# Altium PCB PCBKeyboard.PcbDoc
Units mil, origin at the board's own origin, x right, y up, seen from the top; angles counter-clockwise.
Board outline 2655 x 4800 mil, 2 copper layers (Top Layer, Bottom Layer); 24 components, 13 nets, 98 pads, 4 vias.
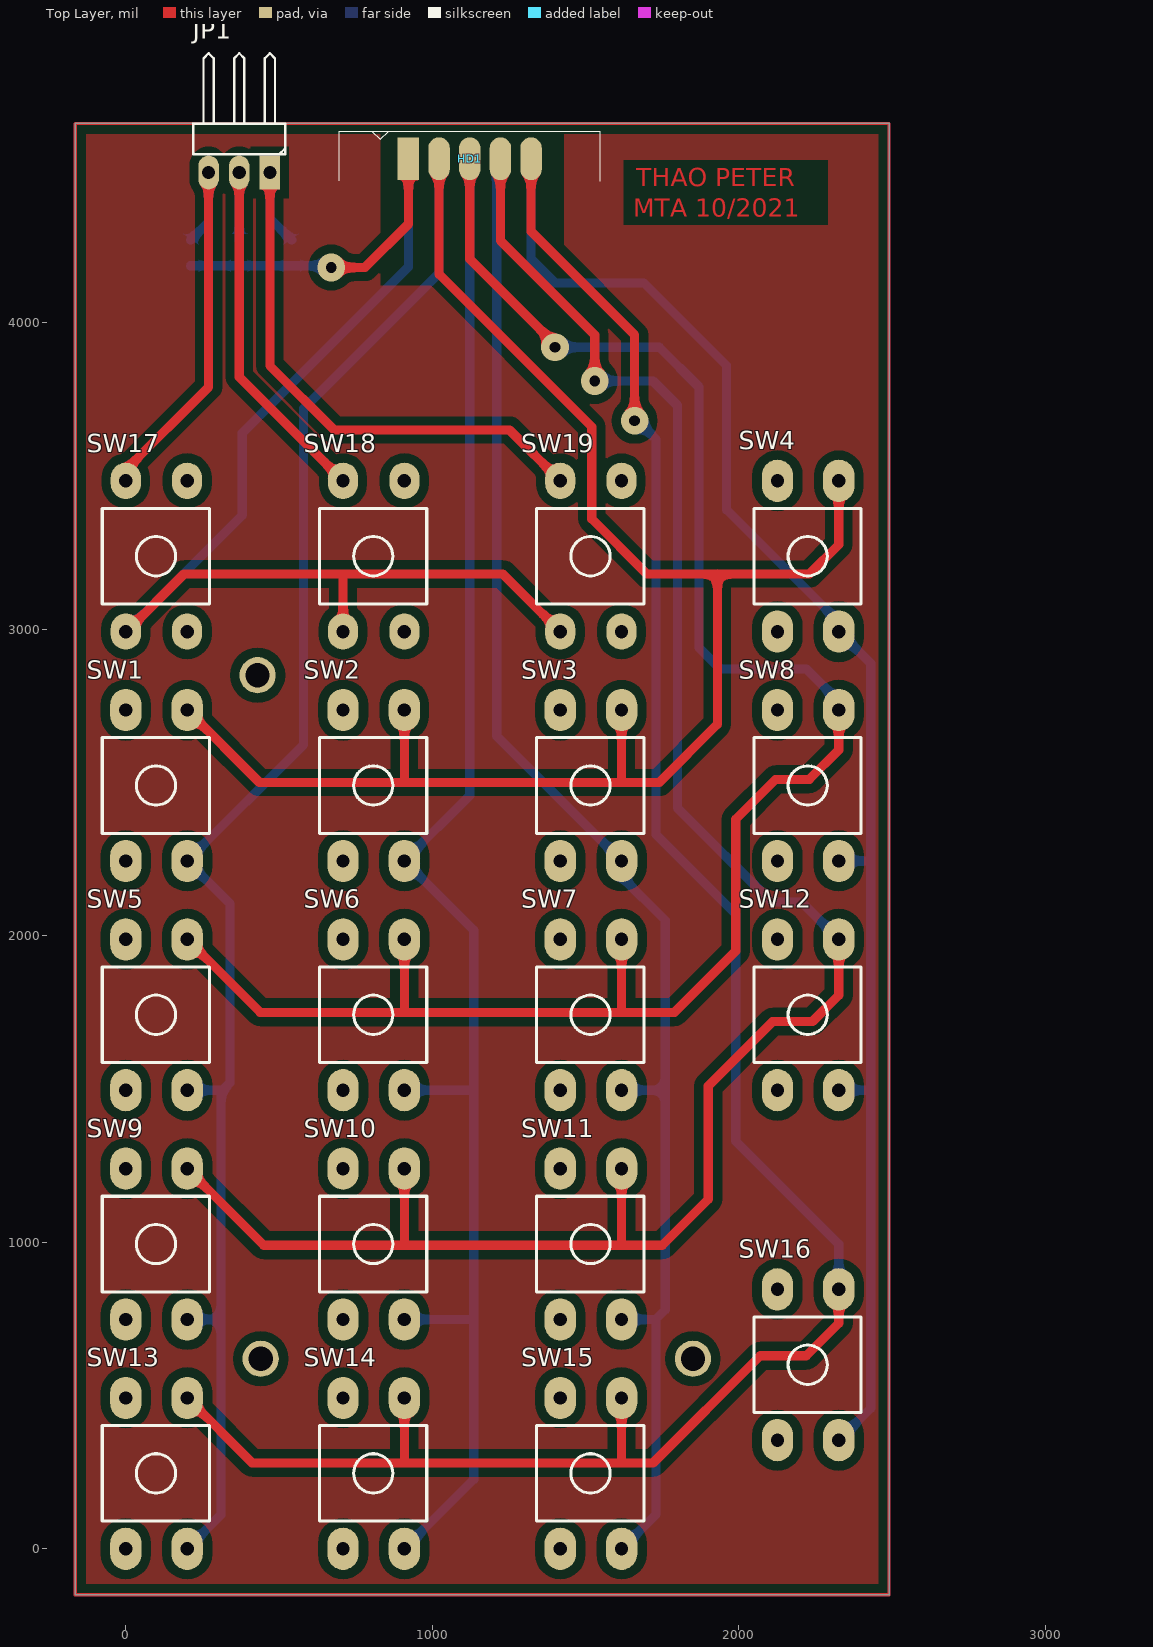
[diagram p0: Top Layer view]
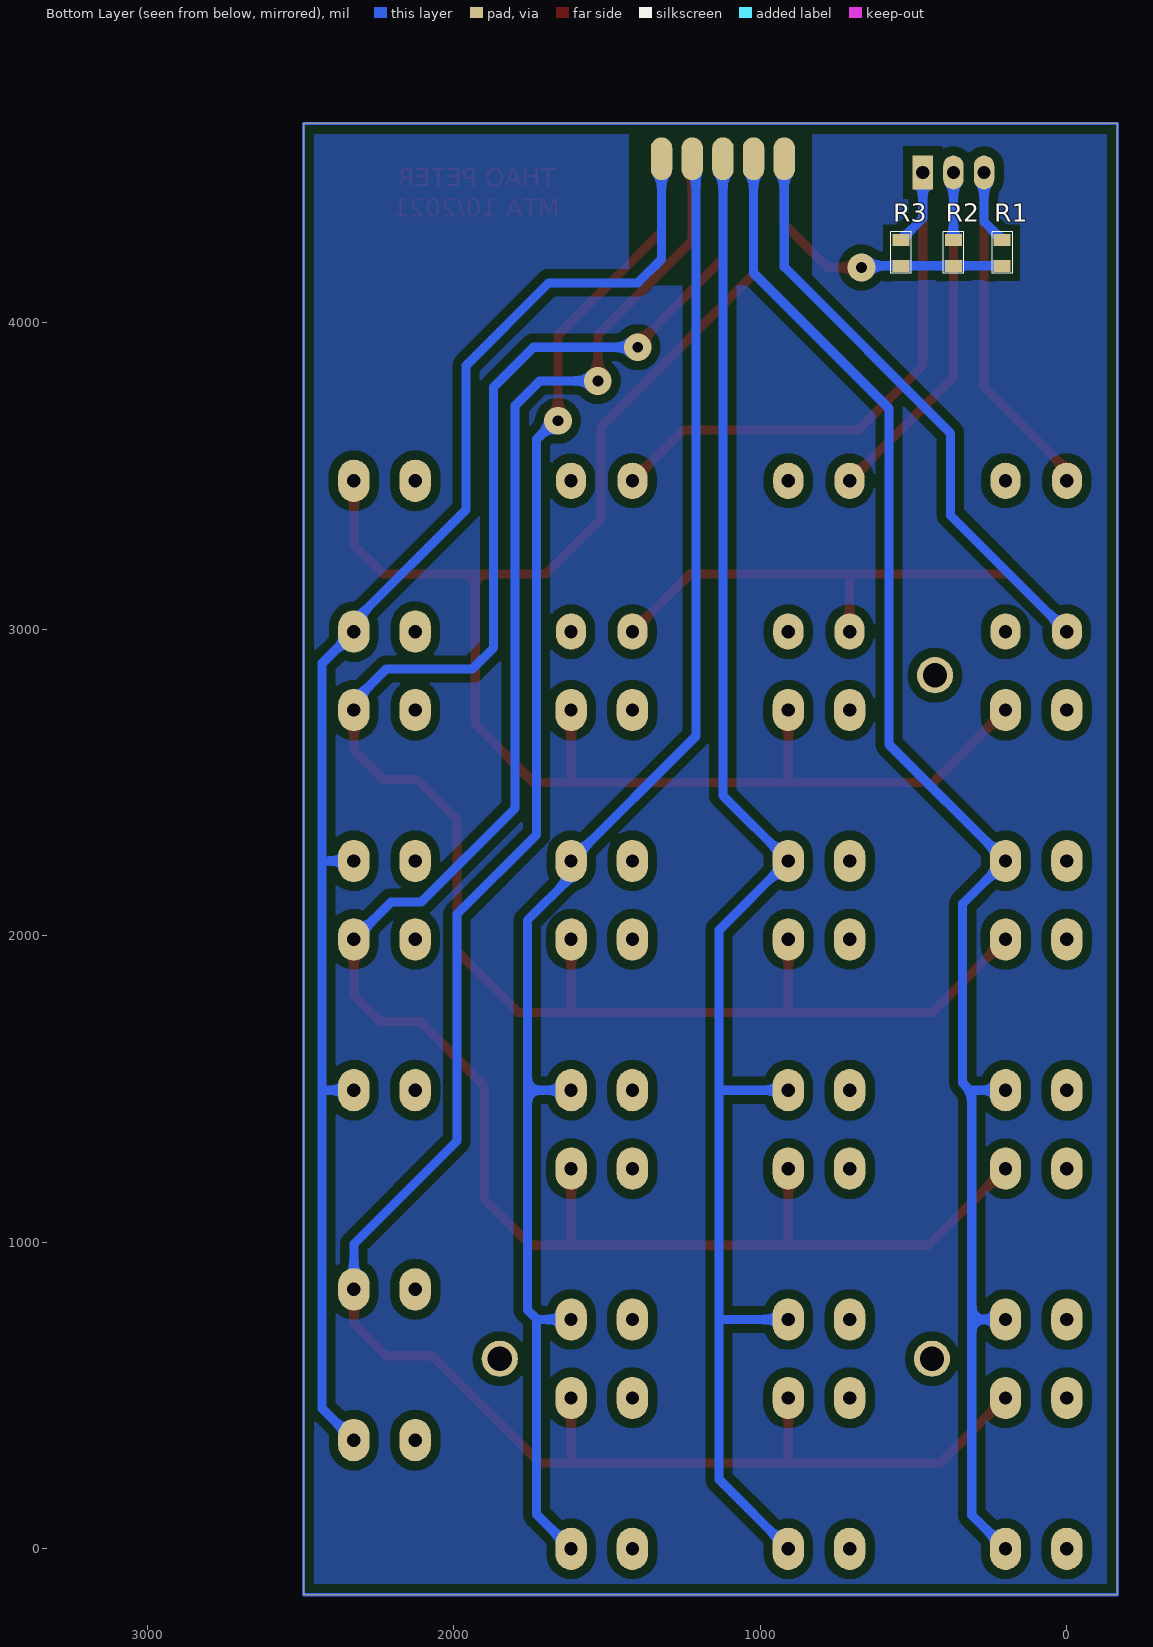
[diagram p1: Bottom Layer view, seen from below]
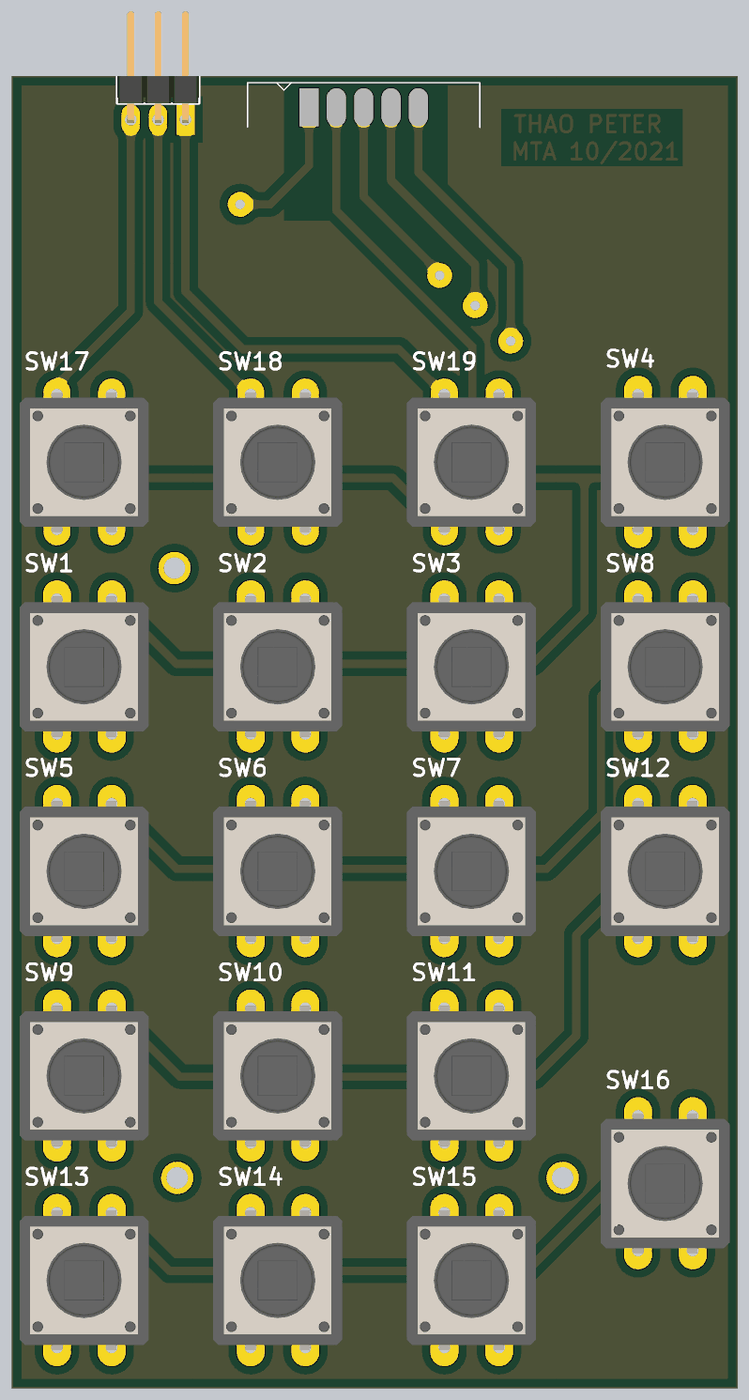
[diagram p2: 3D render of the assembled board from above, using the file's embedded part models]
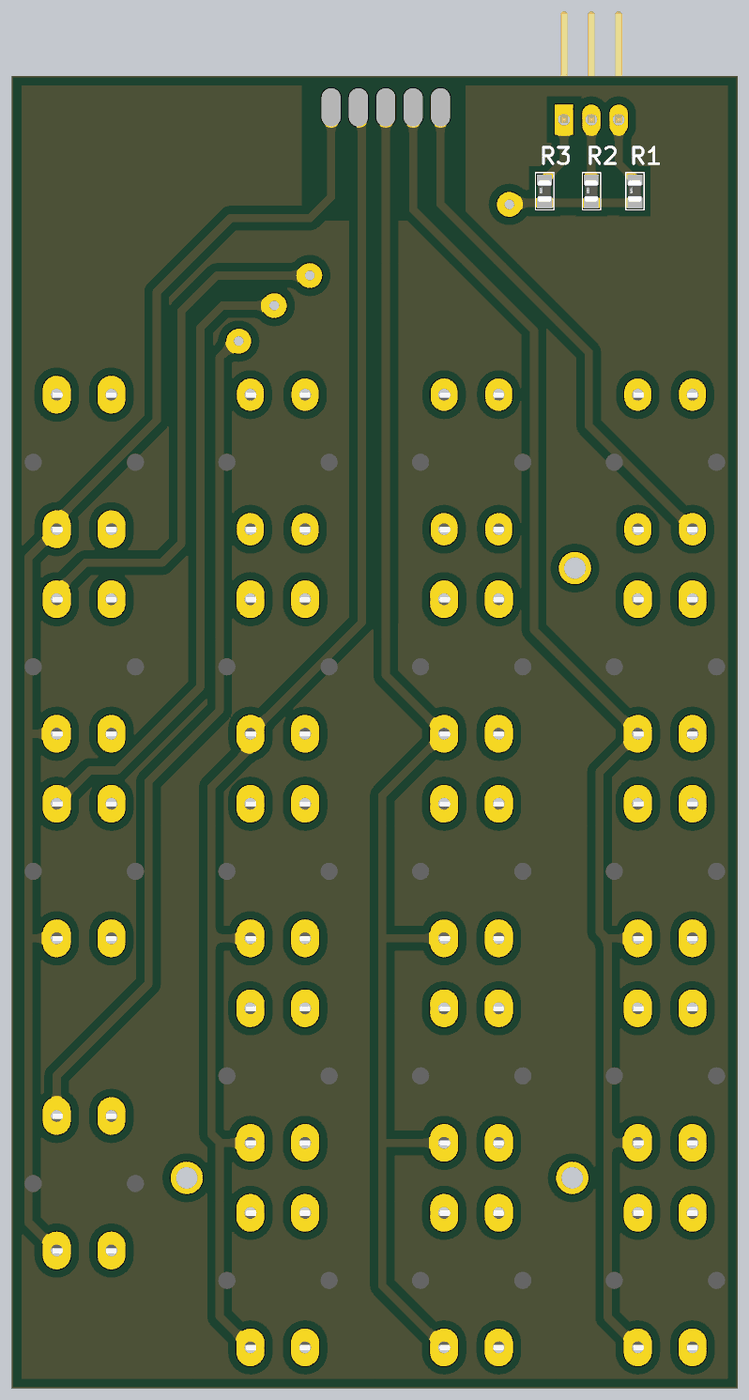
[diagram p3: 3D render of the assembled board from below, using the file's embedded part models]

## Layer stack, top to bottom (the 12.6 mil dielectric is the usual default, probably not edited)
Top Solder: solder mask 0.4, Solder Resist, Dk 3.5
Top Layer: signal copper 1.4
Dielectric 1: dielectric 12.6, FR-4, Dk 4.8
Bottom Layer: signal copper 1.4
Bottom Solder: solder mask 0.4, Solder Resist, Dk 3.5

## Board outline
-165,-150 2490,-150 2490,4650 -165,4650

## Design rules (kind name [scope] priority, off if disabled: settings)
Clearance [All] p1: gap=30 ignorepadtopadclearanceinfootprint=FALSE
PolygonConnect [All] p1: connectstyle=Relief reliefconductorwidth=10 reliefentries=4 polygonreliefangle="90 Angle" airgapwidth=10
RoutingVias [All] p1: holewidth=28 width=50 viastyle="Through Hole" minholewidth=28 minwidth=50 maxholewidth=28 maxwidth=50
SolderMaskExpansion [All] p1: expansion=4
Width [All] p1: maxlimit=100 minlimit=10 preferedwidth=30
30 further rules are at their usual default settings.

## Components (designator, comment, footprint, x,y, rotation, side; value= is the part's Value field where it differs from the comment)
HD1 "IDC 5X2" IDC10-S 1122.05,4700 r0 top value="Header 5x2"
JP1 "JP3" JP3-D1C 220,4590 r180 top
R1 "10k" RES-SMD-0805 211,4185.62 r90 bottom
R2 "10k" RES-SMD-0805 369.99,4185.62 r90 bottom
R3 "10k" RES-SMD-0805 541,4185.62 r90 bottom
SW1 "SW" "BUTTON 12mm"#1 0,2244.09 r90 top value="Button chip 4 pin"
SW2 "SW" "BUTTON 12mm"#1 708.66,2244.09 r90 top value="Button chip 4 pin"
SW3 "SW" "BUTTON 12mm"#1 1417.32,2244.09 r90 top value="Button chip 4 pin"
SW4 "SW" "BUTTON 12mm"#1 2125.98,2992.13 r90 top value="Button chip 4 pin"
SW5 "SW" "BUTTON 12mm"#1 0,1496.06 r90 top value="Button chip 4 pin"
SW6 "SW" "BUTTON 12mm"#1 708.66,1496.06 r90 top value="Button chip 4 pin"
SW7 "SW" "BUTTON 12mm"#1 1417.32,1496.06 r90 top value="Button chip 4 pin"
SW8 "SW" "BUTTON 12mm"#1 2125.98,2244.09 r90 top value="Button chip 4 pin"
SW9 "SW" "BUTTON 12mm"#1 0,748.03 r90 top value="Button chip 4 pin"
SW10 "SW" "BUTTON 12mm"#1 708.66,748.03 r90 top value="Button chip 4 pin"
SW11 "SW" "BUTTON 12mm"#1 1417.32,748.03 r90 top value="Button chip 4 pin"
SW12 "SW" "BUTTON 12mm"#1 2125.98,1496.06 r90 top value="Button chip 4 pin"
SW13 "SW" "BUTTON 12mm"#1 0,0 r90 top value="Button chip 4 pin"
SW14 "SW" "BUTTON 12mm"#1 708.66,0 r90 top value="Button chip 4 pin"
SW15 "SW" "BUTTON 12mm"#1 1417.32,0 r90 top value="Button chip 4 pin"
SW16 "SW" "BUTTON 12mm"#1 2125.98,354.33 r90 top value="Button chip 4 pin"
SW17 "SW" "BUTTON 12mm"#2 0,2992.13 r90 top value="Button chip 4 pin"
SW18 "SW" "BUTTON 12mm"#2 708.66,2992.13 r90 top value="Button chip 4 pin"
SW19 "SW" "BUTTON 12mm"#2 1417.32,2992.13 r90 top value="Button chip 4 pin"

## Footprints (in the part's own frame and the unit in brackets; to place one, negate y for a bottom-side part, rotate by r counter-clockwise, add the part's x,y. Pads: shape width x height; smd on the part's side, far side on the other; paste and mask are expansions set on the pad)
"BUTTON 12mm"#1 [mm]
  oval 3.5x2.6 hole 1.1: 1(0,0) 2(12.5,0) 3(12.5,-5.08) 4(0,-5.08)
  silkscreen extent 2.29,-6.93 10.21,1.96, body extent -0.28,-8.51 12.72,3.49, height 7.3
"BUTTON 12mm"#2 [mm]
  oval 3x2.5 hole 1.1: 1(0,0) 2(12.5,0) 3(12.5,-5.08) 4(0,-5.08)
  silkscreen extent 2.29,-6.93 10.21,1.96, body extent -0.28,-8.51 12.72,3.49, height 7.3
IDC10-S [mil]
  rect 70x140 smd: 1(-200,-165)
  oval 70x140 smd far side: 2(-200,-165) 4(-100,-165) 6(0,-165) 8(100,-165) 10(200,-165)
  oval 70x140 smd: 3(-100,-165) 5(0,-165) 7(100,-165) 9(200,-165)
  silkscreen extent -425,-239 425,-75, body extent -425,-238 426,276, height 151
JP3-D1C [mm] "3 pins, 1 row, right angled, gold plating"
  rect 1.7x2.8 hole 1.1: 1(-6.35,2.54)
  oval 1.7x2.8 hole 1.1: 2(-3.81,2.54) 3(-1.27,2.54)
  silkscreen extent -7.62,-7.34 0,1.04, body extent -7.62,-7.52 0,2.84, height 2.55
RES-SMD-0805 [mil]
  rect 39.37x55 smd: 1(0,0) 2(84.38,0.01)
  silkscreen extent -25,-34 111,33, body extent 4,-25 83,25, height 31

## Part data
HD1: "Header, 5X2-Pin"
JP1: "WR-PHD 2.54 mm Angled Socket Header", Manufacturer="Würth Elektronik eiSos GmbH", partNo=613003143121
R1 R2 R3: library part "Res SMD", "Resistor SMD", Manufacturer="Generic Components"
SW1 SW2 SW3 SW4 SW5 SW6 SW7 SW8 SW9 SW10 SW11 SW12 SW13 SW14 SW15 SW16 SW17 SW18 SW19: library part SW4, "Switch button 4 pin"

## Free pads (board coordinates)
  round 118.11 hole 78.74: 7(430,2850) 7(440,620) 7(1850,620)

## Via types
v1: diameter 90.55, hole 35.43, Top Layer to Bottom Layer, 4 vias

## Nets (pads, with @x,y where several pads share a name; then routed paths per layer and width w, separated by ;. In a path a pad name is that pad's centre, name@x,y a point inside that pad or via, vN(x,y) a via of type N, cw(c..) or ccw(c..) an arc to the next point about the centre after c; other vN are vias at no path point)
1: HD1.3 SW1.3 SW2.3 SW3.3 SW4.3 | length 5383.5
  Top Layer w30: SW1.3 436.22,2500 900,2500 ; SW2.3 908.66,2508.66 900,2500 ; HD1.3 1022.05,4157.95 1520,3660 1520,3360 1700,3180 1930,3180 ; SW3.3 1617.32,2502.68 1620,2500 ; SW4.3 2325.98,3275.98 2230,3180 1930,3180 ; 900,2500 1620,2500 ; 1620,2500 1740,2500 1930,2690 1930,3180
2: HD1.5 SW5.3 SW6.3 SW7.3 SW8.3 | length 6105
  Top Layer w30: SW5.3 438.19,1750 900,1750 ; SW6.3 908.66,1758.66 900,1750 ; HD1.5 1122.05,4207.95 1400,3930 v1(1400,3920) ; SW7.3 1617.32,1757.32 1610,1750 ; SW8.3 2325.98,2605.98 2230,2510 2120,2510 1990,2380 1990,1950 1790,1750 1610,1750 ; 900,1750 1610,1750
  Bottom Layer w30: v1(1400,3920) 1740,3920 1870,3790 1870,2940 1940,2870 2220,2870 2325.98,2764.02 SW8.3
3: HD1.7 SW9.3 SW10.3 SW11.3 SW12.3 | length 6644.2
  Top Layer w30: SW9.3 450.16,990 900,990 ; SW10.3 908.66,998.66 900,990 ; HD1.7 1222.05,4267.95 1530,3960 v1(1530,3810) ; SW11.3 1617.32,992.68 1620,990 ; SW12.3 2325.98,1805.98 2240,1720 2110,1720 1900,1510 1900,1140 1750,990 1620,990 ; 900,990 1620,990
  Bottom Layer w30: v1(1530,3810) 1720,3810 1800,3730 1800,2416.34 2106.34,2110 2204.17,2110 SW12.3
4: HD1.9 SW13.3 SW14.3 SW15.3 SW16.3 | length 7039.4
  Top Layer w30: SW13.3 412.13,280 910,280 ; SW14.3 908.66,281.34 910,280 ; HD1.9 1322.05,4297.95 1660,3960 v1(1660,3680) ; SW15.3 1617.32,282.68 1620,280 ; SW16.3 2325.98,735.98 2220,630 2070,630 1720,280 1620,280 ; 910,280 1620,280
  Bottom Layer w30: v1@1670,3680 1730,3620 1730,2330 1990,2070 1990,1330 2325.98,994.02 SW16.3
5: HD1.10 SW4.4 SW8.4 SW12.4 SW16.4 | length 5065.6
  Bottom Layer w30: HD1.10 1322.05,4207.95 1400,4130 1690,4130 1960,3860 1960,3390 2325.98,3024.02 SW4.4 2430,2888.11 2430,2250 ; SW16.4 2430,458.35 2430,1490 ; SW12.4 2423.94,1496.06 2430,1490 ; SW8.4 2424.09,2244.09 2430,2250 ; 2430,1490 2430,2250
6: HD1.8 SW3.4 SW7.4 SW11.4 SW15.4 | length 5077.3
  Bottom Layer w30: HD1.8@1210,4535 1210,2651.42 SW3.4 1617.32,2192.68 1760,2050 1760,1496.06 ; SW15.4 1730,112.68 1730,748.03 ; SW11.4 1730,748.03 ; SW7.4 1760,1496.06 ; 1730,748.03 1730,750 1760,780 1760,1496.06
7: HD1.6 SW2.4 SW6.4 SW10.4 SW14.4 | length 5266
  Bottom Layer w30: SW14.4 1135,226.34 1135,750 ; SW10.4 1133.03,748.03 1135,750 ; SW6.4 1131.06,1496.06 1135,1500 ; HD1.6 1122.05,4177.95 1122.05,2457.48 SW2.4 1135,2017.76 1135,1500 ; 1135,750 1135,1500
8: HD1.4 SW1.4 SW5.4 SW9.4 SW13.4 | length 5217.5
  Bottom Layer w30: SW13.4 310,110 310,748.03 ; SW9.4 310,748.03 ; SW5.4 310,1496.06 310,1490 ; HD1.4 1022.05,4162.05 580,3720 580,2624.09 SW1.4 340,2104.09 340,1520 310,1490 ; 310,748.03 310,1490
9: JP1.3 R1.2 SW17.2 | length 1362
  Top Layer w30: SW17.2 0,3520 270,3790 JP1.3
  Bottom Layer w30: R1.2 270,4328.99 JP1.3
10: JP1.2 R2.2 SW18.2 | length 1366
  Top Layer w30: JP1.2 370,3822.91 SW18.2
  Bottom Layer w30: R2.2 JP1.2
11: JP1.1 R3.2 SW19.2 | length 1982.4
  Top Layer w30: JP1.1 470,3860 680,3650 1251.57,3650 SW19.2
  Bottom Layer w30: JP1.1 470,4341.01 R3.2
+5: HD1.1 R1.1 R2.1 R3.1 | length 1005.2
  Top Layer w30: v1@650,4180 v1(670,4180) 780,4180 922.05,4322.05 HD1.1
  Bottom Layer w30: R1.1 R2.1 R3.1 664.38,4185.62 v1(670,4180)
GND: HD1.2 SW17.1 SW18.1 SW19.1 | length 3686.1
  Top Layer w30: SW17.1 2.13,2992.13 190,3180 709.72,3180 ; SW18.1 708.66,3178.94 709.72,3180 ; SW19.1 1229.45,3180 709.72,3180
  Bottom Layer w30: SW17.1 380,3372.13 380,3640 922.05,4182.05 HD1.2
pads on no net: SW1.1 SW1.2 SW2.1 SW2.2 SW3.1 SW3.2 SW4.1 SW4.2 SW5.1 SW5.2 SW6.1 SW6.2 SW7.1 SW7.2 SW8.1 SW8.2 SW9.1 SW9.2 SW10.1 SW10.2 SW11.1 SW11.2 SW12.1 SW12.2 SW13.1 SW13.2 SW14.1 SW14.2 SW15.1 SW15.2 SW16.1 SW16.2 SW17.3 SW17.4 SW18.3 SW18.4 SW19.3 SW19.4
copper on no net: | length 29820
  Top Layer w10: -165,-150 -165,4650 2490,4650 2490,-150 -165,-150
  Bottom Layer w10: -165,-150 -165,4650 2490,4650 2490,-150 -165,-150

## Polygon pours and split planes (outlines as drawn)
no net on Top Layer (solid, pour order 8): -165,4650 -165,-150 2490,-150 2490,4650
no net on Bottom Layer (solid, pour order 4): -165,4650 -165,-150 2490,-150 2490,4650

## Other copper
Top Layer:
  pour cut-out: 1625,4530 2290,4530 2290,4320 1625,4320
  pour cut-out: 830,4630 830,4120 1430,4120 1430,4630
  text "THAO PETER" at 1665,4445 h60
  text "MTA 10/2021" at 1655,4345 h60
Bottom Layer:
  pour cut-out: 830,4630 830,4120 1430,4120 1430,4630
  pour cut-out: 3235,2835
